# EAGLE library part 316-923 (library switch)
TOGGLE SWITCH Mors, distributor RS Components
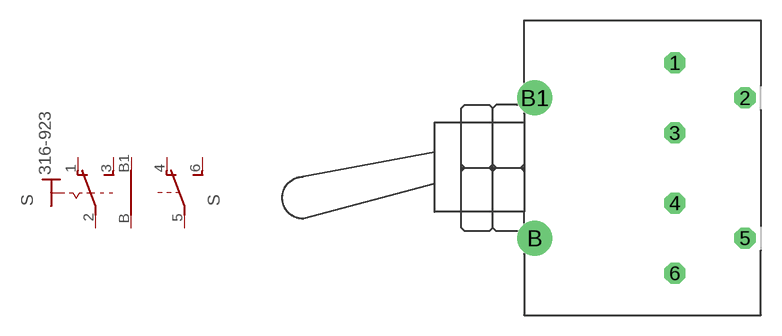
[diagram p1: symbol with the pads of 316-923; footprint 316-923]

Designator prefix S; gates B=U2 2=KS-UB-

## 316-923  [316-923]
1  2:O  pas
2  2:P  pas
3  2:S  pas
4  B:O  pas
5  B:P  pas
6  B:S  pas
B  2:B  pas
B1  2:B1  pas

## Footprint 316-923 (pad centres in mm)
TOGGLE SWITCH Mors, distributor RS Components
drill 1.016 octagon: 1 10.16,7.62; 2 15.24,5.08; 3 10.16,2.54; 4 10.16,-2.54; 5 15.24,-5.08; 6 10.16,-7.62
drill 1.016 pad 2.54 round: B 0,-5.08; B1 0,5.08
